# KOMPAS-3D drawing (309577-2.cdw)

Referenced files: технологический процесс.cdw
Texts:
  КГТУ 00.00.000 ТС
  Установка абсорбционная.  Технологическая схема
  Текст на чертеже
  Размерные надписи
  Шероховатость
  Линия-выноска #1
  Линия-выноска #2
  Линия-выноска #3
  Отклонения формы и база
  Заголовок таблицы
  Ячейка таблицы
  Стрелка вида
  Обозначение изменения
  Фигурная скобка
  Номер узла
  Марка координационной оси
  VRCB
  Выносная надпись
  Обозначение узла
  Марка/позиционное обозначение с линией-выноской
  Марка/позиционное обозначение на линии
  Марка/позиционное обозначение без линии-выноски
  <template><curves><curve offset="10.000000"><style id="0" type="0"/></curve><curve offset="0.000000"><style id="2" type="0"/></curve><curve offset="-10.000000"><style id="0" type="0"/></curve></curves><tips><begin type="0" param="50.000000"><style id="0" type="0"/></begin><end type="0" param="50.000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
  ВР-1
  ВР-2
  ВР-3
  ВР-4
  Условное обозначение
  Букв.
  Графическое
  Наименование среды
  в трубопроводе
  Вода питательная
  Вода с РК
  Смесь азота с этанолом
  Смесь воды с этанолом
  Этаноло РК
  Азот с абсорбера
  Вода оборотная (подача)
  Вода оборотная (возврат)
  Пар
  Конденсат
  ВР1-4
  Абсорбер
  Колонна ректификационная
  Холодильник
  Подогреватель
  Насос
  Вентиль регулирующий
  Кол.
  Приложение 1
  Установка абсорбционная.
  Технологическая схема
  КГТУ 00.00.000 ТС-
Dimensions and other numbers on the sheet: 7; 1; 2; 3; 4; 5; 6; 1:1; 26; 28; 0; 8; 9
